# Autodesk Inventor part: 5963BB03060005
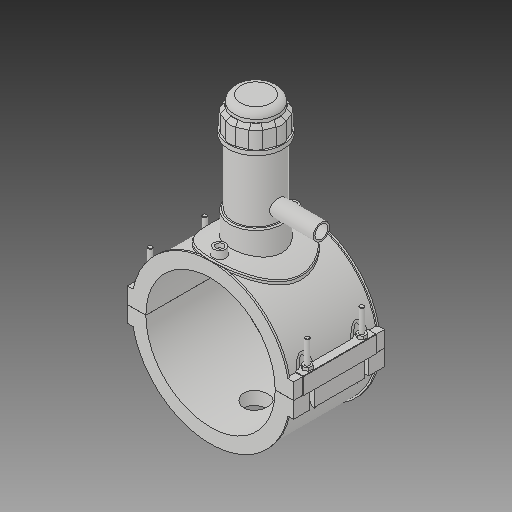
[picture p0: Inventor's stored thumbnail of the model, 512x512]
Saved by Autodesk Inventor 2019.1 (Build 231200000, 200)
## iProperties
Created: 2017-07
Part Number: 5963BB03060005
Material: Generic
Description: PLASSON TAPPING SADDLE 6''IPS x 1 1/2''IPS
Document SubType Name: Modeling
Designer: KIM
Mass: 1712.7 g
Surface Area: 2671.49 cm^2
Volume: 1712.7 cm^3
Density: 1 g/cm^3
Appearance: Default
Author: KIM
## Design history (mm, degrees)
derived "5963B.ipt"
feature "Solid1::5963B.ipt"
feature "Solid2::5963B.ipt"
feature "Solid4::5963B.ipt"
feature "Solid5::5963B.ipt"
tag "TaggingFeature1"
body "Solid1"
body "Solid2"
other parameters: "d0" = 168, "d2" = 215.9, "d3" = 42, "d4" = 118.11, "d5" = 0, "d6" = 0.1, "d8" = 0, "d19" = 6, "d20" = 6, "d21" = 70.866, "d23" = 0, "d24" = 35.433, "d26" = 0, "d29" = 3, "d30" = 56, "d31" = 6, "d32" = 0, "d33" = 0, "d34" = 0.6, "d40" = 104.832, "d41" = 117.6, "d43" = 0, "d45" = 0, "d47" = 171.666, "d70" = 15, "d72" = 0, "d73" = 6, "d75" = 5, "d76" = 0, "d77" = 8.4, "d78" = 114, "d79" = 15, "d80" = 47.244, "d82" = 5 deg, "d84" = 4, "d85" = 14, "d86" = 0, "d87" = 3, "d88" = 0, "d89" = 1, "d90" = 1, "d91" = 94.488, "d92" = 0, "d93" = 0.5, "d94" = 88.42105, "d96" = 205.632, "d97" = 2.3622, "d98" = 0, "d102" = 1.68, "d120" = 140 deg, "d121" = 24.228, "d122" = 20 deg, "d123" = 403.2, "d124" = 120.96, "d126" = 0, "d143" = 173.04, "d145" = 25.84615, "d149" = 2.52, "d150" = 28.43077, "d153" = 118.11, "d154" = 0, "d156" = 100.8, "d157" = 160 deg, "d159" = 6.72, "d161" = 2.52, "d162" = 70.866, "d163" = 0, "d164" = 84, "d167" = 16.8, "d168" = 98.34146, "d170" = 3.2805, "d172" = 0, "d173" = 1, "d175" = 84, "d176" = 20 deg, "d177" = 11.76, "d178" = 33.6, "d180" = 0, "d183" = 13.44, "d184" = 9.408, "d185" = 38.38575, "d186" = 38.38575, "d187" = 100.8, "d188" = 10.08, "d189" = 11.76, "d190" = 0, "d191" = 151.2, "d193" = 6.1236, "d194" = 4.13385, "d195" = 90 deg, "d197" = 0, "d199" = 0, "d200" = 16.8, "d202" = 0, "d203" = 177.038, "d204" = 67.032, "d205" = 49.392, "d206" = 59.976, "d207" = 132.7785, "d208" = 138.08964, "d209" = 164.64534, "d210" = 60.6816, "d211" = 70.56, "d212" = 56.448, "d213" = 48.9816, "d216" = 0, "d217" = 16.8, "d218" = 8.4, "d219" = 1.68, "d222" = 168, "d224" = 0, "d230" = 5.04, "d233" = 6, "d236" = 107.95, "d237" = 35.433, "d238" = 6.02433, "d240" = 35.433, "d241" = 35.433, "d242" = 35.433, "d243" = 6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
